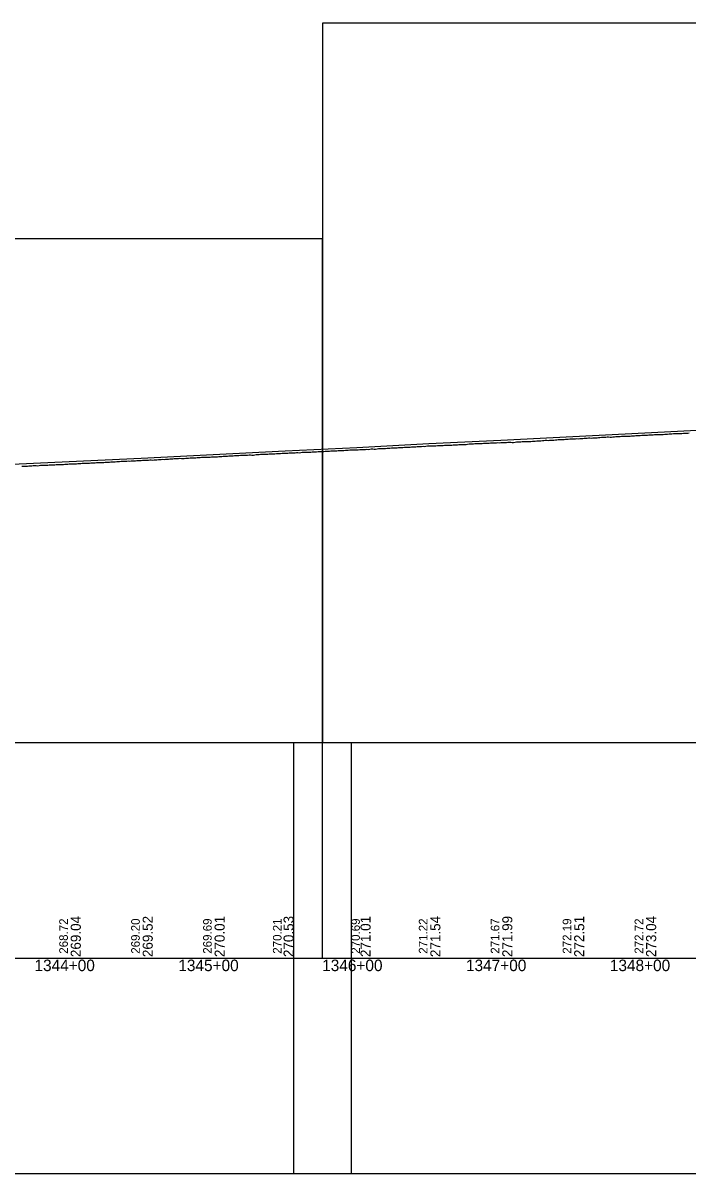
# Model space of a CAD drawing. Extents: x -3627 to 47473, y 2850 to 4350.
# Drawn here: x 21745 to 22207, y 2850 to 3650 of the extents above; entities that cross this region are included whole.
import ezdxf

# ---------------------------------------------------------------- set-up
doc = ezdxf.new("R2010")
doc.units = 0
for name, color, linetype in [('RD_DDB_Profile_EX', 7, 'Continuous'), ('RD_DDB_Profile_PR', 7, 'Continuous'), ('RD_DDB_StaTX', 7, 'Continuous'), ('RD_DDB_StripGrade', 7, 'Continuous'), ('RD_GPK_Profile_Cell', 7, 'Continuous'), ('RD_SHT_ShtClip', 7, 'Continuous')]:
    doc.layers.add(name, color=color, linetype=linetype)

msp = doc.modelspace()

# ---------------------------------------------------------------- linework, layer by layer
at = {"layer": 'RD_DDB_Profile_EX'}
for points in [[(22021.243306, 3355.605445), (22022.247071, 3355.698625), (22023.239051, 3355.801945), (22024.243505, 3355.705825), (22025.241566, 3355.796525), (22026.24624, 3356.005935), (22027.24437, 3356.101685), (22028.2489, 3356.099785), (22029.240142, 3356.13272), (22030.244819, 3356.125795), (22031.242944, 3356.07706), (22032.247476, 3356.08591), (22033.246457, 3356.315485), (22034.243504, 3356.266525), (22035.241707, 3356.272935), (22036.246322, 3356.375955), (22037.245385, 3356.415895), (22038.249283, 3356.496755), (22039.247485, 3356.55329), (22040.239561, 3356.585365), (22041.244344, 3356.639195), (22042.242624, 3356.639575), (22043.24659, 3356.681425), (22044.246494, 3356.775955), (22045.250459, 3356.79084), (22046.241927, 3356.827595), (22047.245872, 3356.91327), (22048.245058, 3356.95214), (22049.25008, 3357.07411), (22050.24859, 3357.024735), (22051.251996, 3357.05875), (22052.243719, 3357.023435), (22053.242231, 3357.06819), (22054.247324, 3357.215785), (22055.245836, 3357.4364), (22056.249992, 3357.474715), (22057.248519, 3357.46311), (22058.246934, 3357.464905), (22059.245531, 3357.64604), (22060.248956, 3357.669195), (22061.247556, 3357.71333), (22062.251758, 3357.75393), (22063.25133, 3357.798555), (22064.248789, 3357.806645), (22065.247401, 3357.86321), (22066.246086, 3357.863055), (22067.251355, 3357.860485), (22068.25004, 3357.916805), (22069.253463, 3357.977525), (22070.252147, 3358.15774), (22071.250831, 3358.17069), (22072.250527, 3358.22081), (22073.249225, 3358.22061), (22074.247996, 3358.306975), (22075.253482, 3358.351765), (22076.253261, 3358.30151), (22077.252032, 3358.35752), (22078.249962, 3358.413955), (22079.248731, 3358.45687), (22080.255057, 3358.46197), (22081.253839, 3358.498145), (22082.252516, 3358.56222), (22083.246654, 3358.613555), (22084.245341, 3358.605385), (22085.245053, 3358.513885), (22086.251459, 3358.481135), (22087.250148, 3358.776285), (22088.249008, 3358.795375), (22089.247708, 3358.88689), (22090.24753, 3358.919035), (22091.252973, 3358.955305), (22092.252799, 3359.04677), (22093.251573, 3359.079215), (22094.251416, 3359.163805), (22095.250372, 3359.227685), (22096.255781, 3359.19147), (22097.255649, 3359.167785), (22098.254512, 3359.215575), (22099.254477, 3359.413635), (22100.254434, 3359.458465), (22101.254404, 3359.463615), (22102.252346, 3359.547345), (22103.252329, 3359.66614), (22104.258901, 3359.673115), (22105.257783, 3359.692495), (22106.25238, 3359.7353), (22107.251356, 3359.88984), (22108.258023, 3359.94661), (22109.256022, 3359.951825), (22110.256147, 3359.919075), (22111.255111, 3360.00837), (22112.261771, 3360.09607), (22113.256472, 3360.053815), (22114.255549, 3360.158595), (22115.26231, 3360.3076), (22116.260357, 3360.355105), (22117.26064, 3360.410445), (22118.2599, 3360.450265), (22119.265608, 3360.48355), (22120.25964, 3360.50869), (22121.260164, 3360.5406)], [(22121.260164, 3360.5406), (22122.259496, 3360.666715), (22123.260075, 3360.710835), (22124.26046, 3360.72019), (22125.254565, 3360.91285), (22126.255134, 3360.93369), (22127.255516, 3360.927545), (22128.256087, 3361.01864), (22129.261966, 3361.059965), (22130.256145, 3361.11022), (22131.255636, 3361.069505), (22132.257305, 3361.170925), (22133.257979, 3361.13792), (22134.257496, 3361.174335), (22135.252617, 3361.394045), (22136.252134, 3361.43087), (22137.252827, 3361.483025), (22138.25456, 3361.571245), (22139.254203, 3361.57253), (22140.249376, 3361.54994), (22141.249018, 3361.600155), (22142.249789, 3361.76034), (22143.251498, 3361.768795), (22144.251161, 3361.77013), (22145.245373, 3361.83434), (22146.25163, 3362.003445), (22147.251485, 3362.05024), (22148.252312, 3362.046585), (22149.252043, 3362.08276), (22150.251904, 3362.182015), (22151.251589, 3362.255735), (22152.257958, 3362.29681), (22153.252349, 3362.234725), (22154.252142, 3362.238975), (22155.252123, 3362.428285), (22156.258561, 3362.468925), (22157.257293, 3362.51568), (22158.252885, 3362.540185), (22159.259299, 3362.580445), (22160.258008, 3362.676775), (22161.257997, 3362.731785), (22162.260171, 3362.756685), (22163.258959, 3362.743935), (22164.259042, 3362.841635), (22165.265486, 3362.90519), (22166.258879, 3362.92751), (22167.260099, 3362.94056), (22168.266515, 3363.038525), (22169.267625, 3363.097915), (22170.261123, 3363.15496), (22171.262318, 3363.26408), (22172.264671, 3363.34585), (22173.258176, 3363.325945), (22174.264676, 3363.378115), (22175.265871, 3363.478055), (22176.266843, 3363.43648), (22177.261765, 3363.607725), (22178.263067, 3363.607555), (22179.264369, 3363.59824), (22180.269535, 3363.713705), (22181.265764, 3363.761465), (22182.267065, 3363.75199), (22183.266932, 3363.77011), (22184.268233, 3363.960615), (22185.2633, 3363.958835), (22186.269729, 3363.976605), (22187.271137, 3364.01652), (22188.266321, 3364.016245), (22189.267731, 3364.04637), (22190.268907, 3364.023415), (22191.270317, 3364.24212), (22192.270473, 3364.21151), (22193.271901, 3364.30117), (22194.265954, 3364.397795), (22195.268974, 3364.35708), (22196.269226, 3364.41657), (22197.270742, 3364.60698), (22198.265784, 3364.609205), (22199.2673, 3364.687545), (22200.267551, 3364.747015), (22201.270594, 3364.687735), (22202.270949, 3364.686985), (22203.27257, 3364.794675), (22204.274192, 3364.873725), (22205.274532, 3364.942875), (22206.270969, 3364.913695), (22207.272836, 3364.95358), (22208.274458, 3365.152445)], [(21921.257339, 3350.74929), (21922.260824, 3350.718175), (21923.256764, 3350.749225), (21924.25835, 3350.871085), (21925.260915, 3350.924515), (21926.263517, 3351.06679), (21927.26033, 3351.031075), (21928.256276, 3351.03904), (21929.258894, 3351.131355), (21930.254921, 3351.232345), (21931.264086, 3351.268965), (21932.260117, 3351.276585), (21933.257146, 3351.290975), (21934.258829, 3351.332725), (21935.255713, 3351.433305), (21936.258402, 3351.4224), (21937.260379, 3351.35341), (21938.257627, 3351.411665), (21939.258707, 3351.604075), (21940.25512, 3351.61273), (21941.257188, 3351.63619), (21942.253602, 3351.756685), (21943.256553, 3351.761025), (21944.258628, 3351.76), (21945.255057, 3351.81251), (21946.257322, 3351.94214), (21947.25382, 3351.944335), (21948.251099, 3351.988535), (21949.254329, 3351.99276), (21950.249901, 3352.08831), (21951.246388, 3352.157865), (21952.255341, 3352.11456), (21953.251698, 3352.077165), (21954.255061, 3352.263035), (21955.251625, 3352.296995), (21956.247306, 3352.3537), (21957.250696, 3352.45725), (21958.247981, 3352.502435), (21959.250243, 3352.55041), (21960.252776, 3352.653675), (21961.24935, 3352.57154), (21962.246699, 3352.56631), (21963.249333, 3352.752445), (21964.245965, 3352.808685), (21965.24947, 3352.856275), (21966.251801, 3352.870175), (21967.248288, 3352.83117), (21968.251805, 3352.878455), (21969.248445, 3353.068265), (21970.244314, 3352.995205), (21971.247918, 3353.17601), (21972.245297, 3353.22056), (21973.248085, 3353.22798), (21974.244782, 3353.322925), (21975.248403, 3353.37528), (21976.244953, 3353.380135), (21977.242602, 3353.444405), (21978.24682, 3353.43509), (21979.243296, 3353.48373), (21980.247514, 3353.6052), (21981.24399, 3353.643655), (21982.248208, 3353.64457), (21983.245343, 3353.642955), (21984.24876, 3353.683325), (21985.246049, 3353.632145), (21986.24382, 3353.735415), (21987.241167, 3353.923595), (21988.244658, 3353.958525), (21989.241208, 3353.866905), (21990.245497, 3353.843345), (21991.248986, 3354.023015), (21992.246335, 3354.171415), (21993.249831, 3354.216505), (21994.247256, 3354.274905), (21995.245101, 3354.327845), (21996.241722, 3354.27562), (21997.246083, 3354.325785), (21998.242704, 3354.513025), (21999.247065, 3354.573725), (22000.244365, 3354.471135), (22001.247913, 3354.655005), (22002.245439, 3354.68631), (22003.24904, 3354.71955), (22004.240879, 3354.71494), (22005.244482, 3354.812825), (22006.248082, 3354.9069), (22007.245618, 3354.89894), (22008.243525, 3354.94624), (22009.247972, 3355.01752), (22010.245957, 3355.11428), (22011.250321, 3355.10756), (22012.242234, 3355.147035), (22013.245913, 3355.2244), (22014.243895, 3355.28228), (22015.247575, 3355.336565), (22016.247071, 3355.34954), (22017.245062, 3355.37295), (22018.241921, 3355.4694), (22019.240801, 3355.555445), (22020.245252, 3355.598225), (22021.243306, 3355.605445)], [(21744.286788, 3341.865575), (21745.293011, 3341.935395), (21746.286411, 3341.97407), (21747.291203, 3342.039575), (21748.283356, 3341.967875), (21749.289623, 3342.18712), (21750.289196, 3342.247145), (21751.28877, 3342.23763), (21752.289835, 3342.359075), (21753.289418, 3342.40929), (21754.289047, 3342.428665), (21755.290165, 3342.31927), (21756.289794, 3342.52052), (21757.289423, 3342.57041), (21758.289052, 3342.648185), (21759.290169, 3342.7485), (21760.289798, 3342.75814), (21761.288179, 3342.7488), (21762.289351, 3342.71962), (21763.283814, 3342.89263), (21764.283504, 3342.911455), (21765.283193, 3342.960965), (21766.284361, 3342.989995), (21767.284051, 3343.008945), (21768.283741, 3343.17937), (21769.283662, 3343.18956), (21770.283634, 3343.178515), (21771.283605, 3343.168975), (21772.283576, 3343.19976), (21773.285023, 3343.19067), (21774.284994, 3343.4022), (21775.283711, 3343.451215), (21776.283682, 3343.439915), (21777.283664, 3343.580375), (21778.283696, 3343.620575), (21779.283729, 3343.610755), (21780.283762, 3343.681635), (21781.283794, 3343.710395), (21782.282575, 3343.710745), (21783.284079, 3343.88205), (21784.284112, 3343.872215), (21785.284155, 3343.879835), (21786.28517, 3343.973415), (21787.285265, 3344.0038), (21788.280101, 3344.06505), (21789.285153, 3344.12615), (21790.279983, 3344.11841), (21791.280078, 3344.17729), (21792.286376, 3344.33157), (21793.282627, 3344.224585), (21794.282789, 3344.35155), (21795.283866, 3344.40481), (21796.284027, 3344.4594), (21797.277687, 3344.42023), (21798.284077, 3344.461745), (21799.278929, 3344.603835), (21800.27909, 3344.55305), (21801.285497, 3344.617245), (21802.28041, 3344.72742), (21803.280635, 3344.776195), (21804.281992, 3344.72983), (21805.282217, 3344.778605), (21806.277115, 3344.970655), (21807.283595, 3344.93014), (21808.278488, 3344.990165), (21809.277558, 3345.071435), (21810.28014, 3345.165435), (21811.279274, 3345.273215), (21812.279766, 3345.331445), (21813.280989, 3345.342735), (21814.28148, 3345.359845), (21815.275273, 3345.434375), (21816.283194, 3345.490685), (21817.276998, 3345.50084), (21818.277556, 3345.59381), (21819.278846, 3345.56076), (21820.274037, 3345.67084), (21821.279562, 3345.664705)], [(21821.279562, 3345.664705), (21822.27588, 3345.71538), (21823.276044, 3345.75049), (21824.276597, 3345.80809), (21825.277903, 3345.94285), (21826.273134, 3345.99373), (21827.278777, 3346.018025), (21828.275116, 3346.051405), (21829.275372, 3346.104755), (21830.276931, 3346.074), (21831.277356, 3346.097305), (21832.278915, 3346.06594), (21833.272853, 3346.307975), (21834.280979, 3346.34078), (21835.274974, 3346.241105), (21836.276602, 3346.384695), (21837.271675, 3346.38445), (21838.278724, 3346.38438), (21839.272719, 3346.643105), (21840.275416, 3346.677855), (21841.274852, 3346.72587), (21842.27655, 3346.761675), (21843.271688, 3346.627915), (21844.273377, 3346.74512), (21845.272876, 3346.80132), (21846.274574, 3346.953545), (21847.269709, 3347.01116), (21848.276835, 3347.04374), (21849.27217, 3347.127345), (21850.27268, 3347.212025), (21851.273503, 3347.2679), (21852.27527, 3347.23582), (21853.269406, 3347.293635), (21854.272242, 3347.46167), (21855.272756, 3347.36284), (21856.268141, 3347.354495), (21857.269913, 3347.41412), (21858.270512, 3347.573065), (21859.272352, 3347.58225), (21860.268848, 3347.539475), (21861.269448, 3347.674095), (21862.271284, 3347.77522), (21863.271899, 3347.834035), (21864.267329, 3347.83547), (21865.269177, 3347.77662), (21866.269873, 3347.911195), (21867.27282, 3347.91161), (21868.26832, 3347.91871), (21869.269014, 3348.137395), (21870.270924, 3348.177985), (21871.271628, 3348.228485), (21872.267118, 3348.26973), (21873.269041, 3348.25468), (21874.270849, 3348.238565), (21875.272836, 3348.323315), (21876.268405, 3348.356), (21877.269179, 3348.445925), (21878.271165, 3348.486085), (21879.273151, 3348.57864), (21880.267686, 3348.577915), (21881.269684, 3348.70459), (21882.271746, 3348.74685), (21883.273808, 3348.712835), (21884.268419, 3348.861715), (21885.270481, 3348.861875), (21886.271332, 3348.945825), (21887.267917, 3349.04067), (21888.268958, 3349.099175), (21889.265541, 3349.167335), (21890.26768, 3349.217145), (21891.270766, 3349.25583), (21892.271913, 3349.290845), (21893.268534, 3349.34335), (21894.270673, 3349.40825), (21895.267276, 3349.445655), (21896.268442, 3349.51834), (21897.263917, 3349.520265), (21898.266134, 3349.527135), (21899.262801, 3349.70692), (21900.264059, 3349.69205), (21901.260719, 3349.686945), (21902.269453, 3349.77388), (21903.266101, 3349.8551), (21904.268319, 3349.72615), (21905.264032, 3349.73563), (21906.266331, 3349.963205), (21907.263039, 3350.014915), (21908.26441, 3350.12152), (21909.261113, 3350.18027), (21910.262488, 3350.215555), (21911.258268, 3350.217715), (21912.267281, 3350.28342), (21913.263082, 3350.26308), (21914.265456, 3350.26196), (21915.262377, 3350.39986), (21916.258236, 3350.444565), (21917.25972, 3350.586835), (21918.256476, 3350.601765), (21919.265595, 3350.60293), (21920.261461, 3350.56122), (21921.257339, 3350.74929)]]:
    msp.add_lwpolyline(points, dxfattribs=at)
at = {"layer": 'RD_DDB_Profile_PR'}
msp.add_lwpolyline([(21277.33, 3320.287), (21327.33, 3323.026), (21377.33, 3325.6065), (21427.33, 3327.864), (21477.33, 3330.1855), (21527.33, 3332.8545), (21577.33, 3335.4485), (21627.33, 3337.8435), (21677.33, 3340.347), (21727.33, 3342.8005), (21777.33, 3345.182), (21827.33, 3347.6195), (21877.33, 3350.0485), (21927.33, 3352.6315), (21977.33, 3355.0435), (22027.33, 3357.7015), (22077.33, 3359.962), (22127.33, 3362.5345), (22177.33, 3365.2075), (22227.33, 3367.6435)], dxfattribs=at)
at = {"layer": 'RD_GPK_Profile_Cell'}
msp.add_line((1000, 3000), (46705.077602, 3000), dxfattribs=at)
at = {"layer": 'RD_SHT_ShtClip'}
for points in [[(21953.33, 3650), (21953.33, 3150), (23453.33, 3150), (23453.33, 3150), (23453.33, 3650), (23453.33, 3650)], [(20453.33, 3500), (20453.33, 3000), (21953.33, 3000), (21953.33, 3000), (21953.33, 3500), (21953.33, 3500)], [(20433.33, 3150), (21973.33, 3150), (21973.33, 2850), (20433.33, 2850)], [(21933.33, 3150), (23473.33, 3150), (23473.33, 2850), (21933.33, 2850)]]:
    msp.add_lwpolyline(points, close=True, dxfattribs=at)

# ---------------------------------------------------------------- texts
at = {"layer": 'RD_DDB_StaTX'}
for s, p in [('1344+00', (21753.125471, 2991)), ('1345+00', (21853.125471, 2991)), ('1346+00', (21953.125471, 2991)), ('1347+00', (22053.125471, 2991)), ('1348+00', (22153.125471, 2991))]:
    msp.add_text(s, height=8, dxfattribs=at).set_placement(p)
at = {"layer": 'RD_DDB_StripGrade'}
for s, height, p in [('268.72', 6, (21776.33, 3003.073688)), ('269.04', 7, (21785.33, 3000.75)), ('269.20', 6, (21826.33, 3003.073688)), ('269.52', 7, (21835.33, 3000.75)), ('269.69', 6, (21876.33, 3003.073688)), ('270.01', 7, (21885.33, 3000.75)), ('270.21', 6, (21924.896136, 3003.073688)), ('270.53', 7, (21933.28677, 3000.75)), ('270.69', 6, (21979.33, 3003.073688)), ('271.01', 7, (21986.777963, 3000.75)), ('271.22', 6, (22026.33, 3003.073688)), ('271.54', 7, (22035.33, 3000.75)), ('271.67', 6, (22076.33, 3003.073688)), ('271.99', 7, (22085.33, 3000.75)), ('272.19', 6, (22126.33, 3003.073688)), ('272.51', 7, (22135.33, 3000.75)), ('272.72', 6, (22176.33, 3003.073688)), ('273.04', 7, (22185.33, 3000.75))]:
    msp.add_text(s, height=height, rotation=90, dxfattribs=at).set_placement(p)

doc.saveas('drawing.dxf')
